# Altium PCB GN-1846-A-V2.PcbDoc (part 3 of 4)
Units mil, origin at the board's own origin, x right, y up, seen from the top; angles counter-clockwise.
Board outline 11624.17 x 2384.02 mil, 4 copper layers (Top, GND, VCC, Bottom), stack 40.7 mil thick; 450 components, 346 nets, 1652 pads, 832 vias.
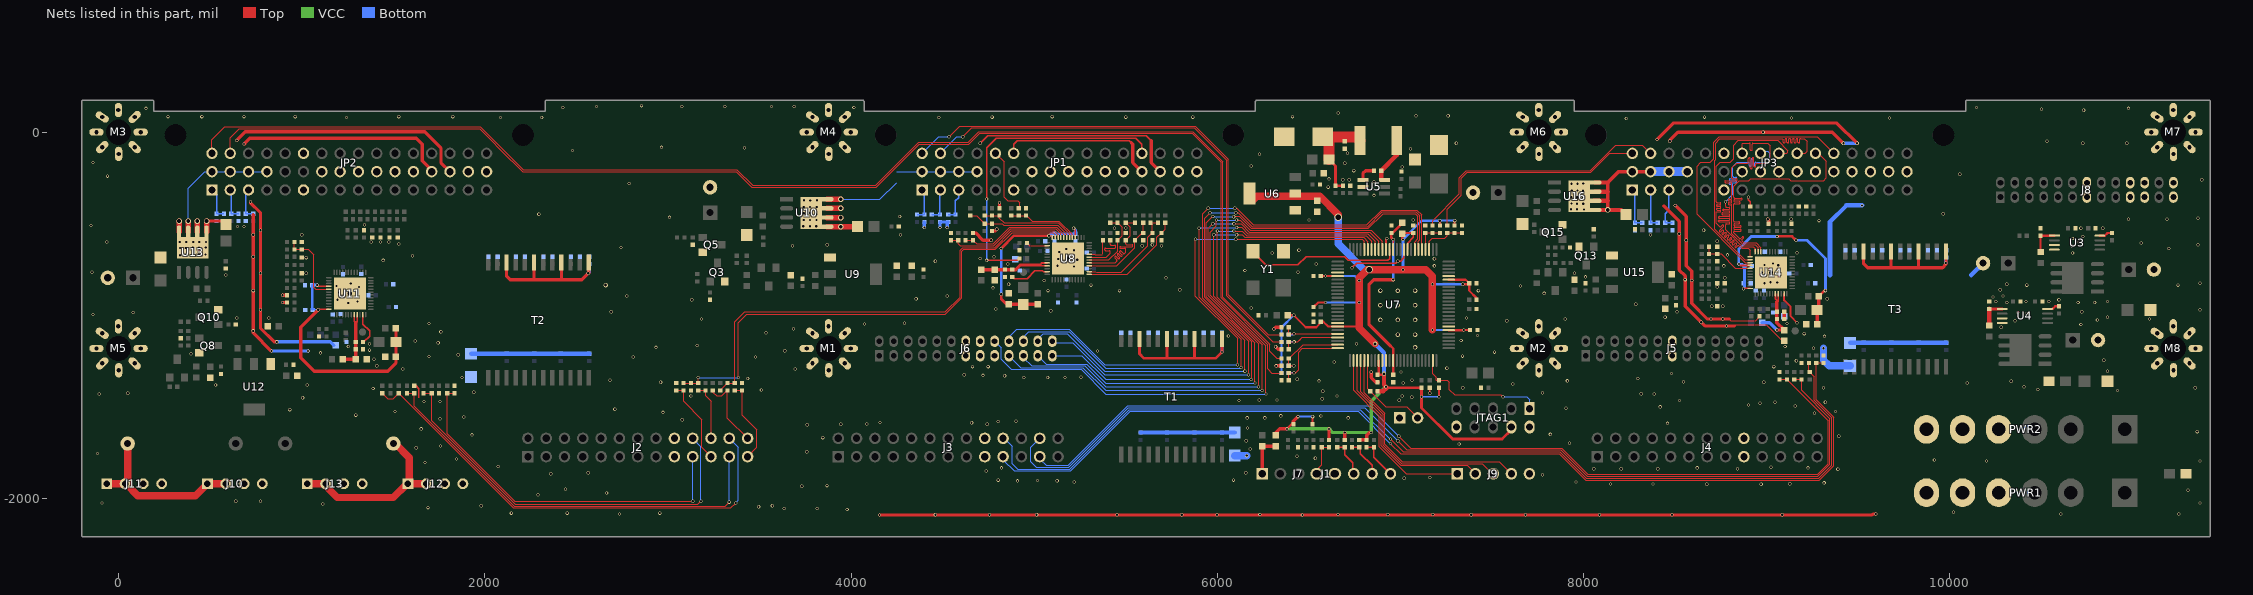
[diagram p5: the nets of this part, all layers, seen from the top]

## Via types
v1: diameter 18, hole 12, Top to Bottom, 768 vias
v2: diameter 24, hole 16, Top to Bottom, 34 vias
v3: diameter 30, hole 20, Top to Bottom, 27 vias
v4: diameter 40, hole 30, Top to Bottom, 2 vias
v5: diameter 24, hole 14, Top to Bottom, 1 vias

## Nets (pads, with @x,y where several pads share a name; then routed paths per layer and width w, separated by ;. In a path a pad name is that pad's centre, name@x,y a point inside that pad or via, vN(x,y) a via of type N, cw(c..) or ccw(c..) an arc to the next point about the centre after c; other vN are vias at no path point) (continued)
CRGMII_TXCKOUT: JP3.A11 U14.22 | length 1539.2
  Top w5: U14.22@8968.27,-651.89 8968.27,-630 8943.27,-605 8875,-605 8863.79,-593.79 cw(c8866.97,-590.61) 8863.79,-587.42 8871.82,-579.39 ccw(c8868.64,-576.21) 8871.82,-573.03 8871.11,-572.32 ccw(c8867.93,-575.5) 8864.75,-572.32 8856.72,-580.35 cw(c8853.54,-577.17) 8850.35,-580.35 8820,-550 8820,-544.5 cw(c8824.5,-544.5) 8824.5,-540 8855.5,-540 ccw(c8855.5,-535.5) 8860,-535.5 8860,-534.5 ccw(c8855.5,-534.5) 8855.5,-530 8824.5,-530 cw(c8824.5,-525.5) 8820,-525.5 8820,-524.5 cw(c8824.5,-524.5) 8824.5,-520 8855.5,-520 ccw(c8855.5,-515.5) 8860,-515.5 8860,-514.5 ccw(c8855.5,-514.5) 8855.5,-510 8824.5,-510 cw(c8824.5,-505.5) 8820,-505.5 8820,-504.5 cw(c8824.5,-504.5) 8824.5,-500 8846.87,-500 ccw(c8846.87,-495.5) 8851.37,-495.5 8851.37,-494.5 ccw(c8846.87,-494.5) 8846.87,-490 8824.5,-490 cw(c8824.5,-485.5) 8820,-485.5 8820,-394.5 cw(c8824.5,-394.5) 8824.5,-390 8849.56,-390 ccw(c8849.56,-385.5) 8854.06,-385.5 8854.06,-384.5 ccw(c8849.56,-384.5) 8849.56,-380 8824.5,-380 cw(c8824.5,-375.5) 8820,-375.5 8820,-374.5 cw(c8824.5,-374.5) 8824.5,-370 8860.5,-370 ccw(c8860.5,-365.5) 8865,-365.5 8865,-364.5 ccw(c8860.5,-364.5) 8860.5,-360 8824.5,-360 cw(c8824.5,-355.5) 8820,-355.5 8820,-295 8850,-265 8902.13,-265 8912.13,-255 9120,-255 9130,-265 9310,-265 9325,-250 9325,-160 9273.14,-108.14 JP3.A11@9265.75,-115.52
CRGMII_TXD0: JP3.A7 U14.23 | length 1537.8
  Top w5: 8770,-270.5 ccw(c8774.5,-270.5) 8774.5,-275 8805.5,-275 cw(c8805.5,-279.5) 8810,-279.5 8810,-360.5 cw(c8805.5,-360.5) 8805.5,-365 8793.73,-365 ccw(c8793.73,-369.5) 8789.23,-369.5 ; 8770,-269.5 cw(c8774.5,-269.5) 8774.5,-265 8834,-265 ccw(c8834,-260.5) 8838.5,-260.5 ; 8789.23,-390.5 ccw(c8793.73,-390.5) 8793.73,-395 8805.5,-395 cw(c8805.5,-399.5) 8810,-399.5 8810,-554.14 8870.86,-615 8937.52,-615 8952.52,-630 U14.23@8952.52,-651.89 ; 8789.23,-389.5 cw(c8793.73,-389.5) 8793.73,-385 8805.5,-385 ccw(c8805.5,-380.5) 8810,-380.5 ; 8789.23,-370.5 ccw(c8793.73,-370.5) 8793.73,-375 8805.5,-375 cw(c8805.5,-379.5) 8810,-379.5 ; 8838.5,-259.5 ccw(c8834,-259.5) 8834,-255 8814.5,-255 cw(c8814.5,-250.5) 8810,-250.5 8810,-195 8835,-170 8895.5,-170 ccw(c8895.5,-165.5) 8900,-165.5 8900,-144.5 cw(c8904.5,-144.5) 8904.5,-140 8905.5,-140 cw(c8905.5,-144.5) 8910,-144.5 8910,-195.5 ccw(c8914.5,-195.5) 8914.5,-200 8915.5,-200 ccw(c8915.5,-195.5) 8920,-195.5 8920,-144.5 cw(c8924.5,-144.5) 8924.5,-140 8925.5,-140 cw(c8925.5,-144.5) 8930,-144.5 8930,-184.96 ccw(c8934.5,-184.96) 8934.5,-189.46 8935.5,-189.46 ccw(c8935.5,-184.96) 8940,-184.96 8940,-174.5 cw(c8944.5,-174.5) 8944.5,-170 9005,-170 9020,-155 9020,-75 9005,-60 8924.5,-60 ccw(c8924.5,-64.5) 8920,-64.5 8920,-95.5 cw(c8915.5,-95.5) 8915.5,-100 8914.5,-100 cw(c8914.5,-95.5) 8910,-95.5 8910,-64.5 ccw(c8905.5,-64.5) 8905.5,-60 8870,-60 8865.75,-64.25 JP3.A7@8865.75,-118.39
CRGMII_TXD1: JP3.A8 U14.24 | length 1563.4
  Top w5: v1(8775,-380) 8775,-405.5 ccw(c8779.5,-405.5) 8779.5,-410 8794.31,-410 cw(c8794.31,-414.5) 8798.81,-414.5 8798.81,-415.5 cw(c8794.31,-415.5) 8794.31,-420 8765.19,-420 ccw(c8765.19,-424.5) 8760.69,-424.5 8760.69,-425.5 ccw(c8765.19,-425.5) 8765.19,-430 8794.31,-430 cw(c8794.31,-434.5) 8798.81,-434.5 8798.81,-435.5 cw(c8794.31,-435.5) 8794.31,-440 8759.46,-440 ccw(c8759.46,-444.5) 8754.96,-444.5 8754.96,-445.5 ccw(c8759.46,-445.5) 8759.46,-450 8794.31,-450 cw(c8794.31,-454.5) 8798.81,-454.5 8798.81,-455.5 cw(c8794.31,-455.5) 8794.31,-460 8740.69,-460 ccw(c8740.69,-464.5) 8736.19,-464.5 8736.19,-465.5 ccw(c8740.69,-465.5) 8740.69,-470 8794.31,-470 cw(c8794.31,-474.5) 8798.81,-474.5 8798.81,-475.5 cw(c8794.31,-475.5) 8794.31,-480 8740.69,-480 ccw(c8740.69,-484.5) 8736.19,-484.5 8736.19,-485.5 ccw(c8740.69,-485.5) 8740.69,-490 8794.31,-490 cw(c8794.31,-494.5) 8798.81,-494.5 8798.81,-495.5 cw(c8794.31,-495.5) 8794.31,-500 8779.5,-500 ccw(c8779.5,-504.5) 8775,-504.5 8775,-533.28 8866.72,-625 8925,-625 8936.78,-636.78 U14.24@8936.78,-651.89
  Bottom w5: v1(8775,-380) 8815,-340 8815,-289.5 ccw(c8810.5,-289.5) 8810.5,-285 8799.5,-285 cw(c8799.5,-280.5) 8795,-280.5 8795,-279.5 cw(c8799.5,-279.5) 8799.5,-275 8830.5,-275 ccw(c8830.5,-270.5) 8835,-270.5 8835,-269.5 ccw(c8830.5,-269.5) 8830.5,-265 8799.5,-265 cw(c8799.5,-260.5) 8795,-260.5 8795,-259.5 cw(c8799.5,-259.5) 8799.5,-255 8830.5,-255 ccw(c8830.5,-250.5) 8835,-250.5 8835,-249.5 ccw(c8830.5,-249.5) 8830.5,-245 8819.5,-245 cw(c8819.5,-240.5) 8815,-240.5 8815,-190 8840,-165 8900.5,-165 cw(c8900.5,-169.5) 8905,-169.5 8905,-180.5 ccw(c8909.5,-180.5) 8909.5,-185 8910.5,-185 ccw(c8910.5,-180.5) 8915,-180.5 8915,-149.5 cw(c8919.5,-149.5) 8919.5,-145 8920.5,-145 cw(c8920.5,-149.5) 8925,-149.5 8925,-180.5 ccw(c8929.5,-180.5) 8929.5,-185 8930.5,-185 ccw(c8930.5,-180.5) 8935,-180.5 8935,-169.5 cw(c8939.5,-169.5) 8939.5,-165 9010,-165 9015,-160 9015,-115 9005,-105 8976.27,-105 JP3.A8@8965.75,-115.52
CRGMII_TXD2: JP3.A9 U14.25 | length 1555.2
  Top w5: 8725,-420.5 ccw(c8729.5,-420.5) 8729.5,-425 8745.42,-425 cw(c8745.42,-429.5) 8749.92,-429.5 ; 8725,-419.5 cw(c8729.5,-419.5) 8729.5,-415 8745.42,-415 ccw(c8745.42,-410.5) 8749.92,-410.5 ; 8725,-400.5 ccw(c8729.5,-400.5) 8729.5,-405 8745.42,-405 cw(c8745.42,-409.5) 8749.92,-409.5 ; 8725,-399.5 cw(c8729.5,-399.5) 8729.5,-395 8745.42,-395 ccw(c8745.42,-390.5) 8749.92,-390.5 ; 8749.92,-430.5 cw(c8745.42,-430.5) 8745.42,-435 8725,-435 8725,-497.43 8742.82,-515.25 ccw(c8746,-512.06) 8749.18,-515.25 8756.61,-507.82 cw(c8759.79,-511) 8762.98,-507.82 8763.68,-508.52 cw(c8760.5,-511.7) 8763.68,-514.89 8742.04,-536.53 ccw(c8745.22,-539.72) 8742.04,-542.9 8742.74,-543.6 ccw(c8745.93,-540.42) 8749.11,-543.6 8756.96,-535.75 cw(c8760.14,-538.93) 8763.32,-535.75 8764.03,-536.46 cw(c8760.85,-539.64) 8764.03,-542.82 8756.18,-550.68 ccw(c8759.36,-553.86) 8756.18,-557.04 8756.89,-557.75 ccw(c8760.07,-554.56) 8763.25,-557.75 8771.1,-549.89 cw(c8774.29,-553.08) 8777.47,-549.89 8778.17,-550.6 cw(c8774.99,-553.78) 8778.17,-556.96 8770.32,-564.82 ccw(c8773.5,-568) 8770.32,-571.18 8771.03,-571.89 ccw(c8774.21,-568.71) 8777.39,-571.89 8785.25,-564.04 cw(c8788.43,-567.22) 8791.61,-564.04 8792.32,-564.74 cw(c8789.13,-567.92) 8792.32,-571.11 8784.46,-578.96 ccw(c8787.65,-582.14) 8784.46,-585.32 8785.17,-586.03 ccw(c8788.35,-582.85) 8791.53,-586.03 8799.39,-578.18 cw(c8802.57,-581.36) 8805.75,-578.18 8806.46,-578.88 cw(c8803.28,-582.07) 8806.46,-585.25 8798.61,-593.1 ccw(c8801.79,-596.28) 8798.61,-599.47 8799.31,-600.17 ccw(c8802.49,-596.99) 8805.68,-600.17 8813.53,-592.32 cw(c8816.71,-595.5) 8819.89,-592.32 8820.6,-593.03 cw(c8817.42,-596.21) 8820.6,-599.39 8812.75,-607.24 ccw(c8815.93,-610.43) 8812.75,-613.61 8813.45,-614.32 ccw(c8816.64,-611.13) 8819.82,-614.32 8827.67,-606.46 cw(c8830.85,-609.64) 8834.04,-606.46 8834.74,-607.17 cw(c8831.56,-610.35) 8834.74,-613.53 8826.89,-621.39 ccw(c8830.07,-624.57) 8826.89,-627.75 8827.6,-628.46 ccw(c8830.78,-625.28) 8833.96,-628.46 8841.81,-620.6 cw(c8845,-623.79) 8848.18,-620.6 8862.57,-635 8900,-635 8908.43,-643.43 U14.25@8908.43,-680.24 ; 8749.92,-389.5 ccw(c8745.42,-389.5) 8745.42,-385 8729.5,-385 cw(c8729.5,-380.5) 8725,-380.5 8725,-185 8745,-165 8800,-165 8820,-145 8820,-70 8845,-45 9060,-45 9115,-100 9115,-110 9109.48,-115.52 JP3.A9@9065.75,-115.52
CRGMII_TXD3: JP3.A10 U14.26 | length 1560.5
  Top w5: U14.26@8908.43,-695.98 8880.98,-695.98 8715,-530 8715,-154.14 8720,-149.14 8720,-59.14 8744.14,-35 9085,-35 9090,-40 9090,-54.02 ccw(c9094.5,-54.02) 9094.5,-58.52 9095.5,-58.52 ccw(c9095.5,-54.02) 9100,-54.02 9100,-39.5 cw(c9104.5,-39.5) 9104.5,-35 9105.5,-35 cw(c9105.5,-39.5) 9110,-39.5 9110,-54.02 ccw(c9114.5,-54.02) 9114.5,-58.52 9115.5,-58.52 ccw(c9115.5,-54.02) 9120,-54.02 9120,-39.5 cw(c9124.5,-39.5) 9124.5,-35 9125.5,-35 cw(c9125.5,-39.5) 9130,-39.5 9130,-54.02 ccw(c9134.5,-54.02) 9134.5,-58.52 9135.5,-58.52 ccw(c9135.5,-54.02) 9140,-54.02 9140,-39.5 cw(c9144.5,-39.5) 9144.5,-35 9145.5,-35 cw(c9145.5,-39.5) 9150,-39.5 9150,-54.02 ccw(c9154.5,-54.02) 9154.5,-58.52 9155.5,-58.52 ccw(c9155.5,-54.02) 9160,-54.02 9160,-39.5 cw(c9164.5,-39.5) 9164.5,-35 9165.5,-35 cw(c9165.5,-39.5) 9170,-39.5 9170,-54.02 ccw(c9174.5,-54.02) 9174.5,-58.52 9175.5,-58.52 ccw(c9175.5,-54.02) 9180,-54.02 9180,-39.5 cw(c9184.5,-39.5) 9184.5,-35 9205,-35 9220,-50 9220,-105 9209.48,-115.52 JP3.A10@9165.75,-115.52
CRGMII_TXEN: JP3.A12 U14.27 | length 1563.4
  Top w5: U14.27@8908.43,-711.73 8882.59,-711.73 8620,-449.14 8620,-185 8640,-165 8690,-165 8710,-145 8710,-55 8740,-25 9275.62,-25 JP3.A12@9365.75,-115.13
EPHY_CLK: JP1.A13 R39.1 | length 1731.5
  Top w8: v1(4740,-700) 4910,-700 R39.1@4920,-690 ; v1(4740,-365) 4740,-85 4791.85,-33.15 5555.11,-33.15 5587.8,-65.84 JP1.A13@5587.8,-115.41
  Bottom w8: v1(4740,-700) v1(4740,-365)
EPHY_RSTN: JP1.A5 R35.1 | length 386.6
  Top w5: JP1.A5@4787.8,-115.41 4835,-162.61 4835,-355 4855,-375 4910,-375 4920,-385 R35.1@4920,-415
F3V3A: B2.2 C26.1 C27.1 U7.13 U7.63 | length 1088.8
  Top w8: C26.1@6950,-550 C26.1@6955.47,-550 ; U7.63@6959.81,-640.27 6960,-640.08 v1(6960,-585.84)
  Top w12: 6943.15,-1165.84 6944.81,-1165.84 6959.81,-1180.84 U7.13@6959.81,-1246.56 C27.1@6959.81,-1324.81
  Top w15: C26.1@6950,-550 6950,-575.84 v1(6960,-585.84) ; C26.1@6955.47,-550 B2.2@7010,-495.47
  Top w18: 6943.15,-1165.84 6828.15,-1050.84 6828.15,-830 6853.15,-805 v1(6960,-805)
  Bottom w15: v1(6960,-805) v1(6960,-585.84)
F3V3D: B1.1 B2.1 B13.2 C14.1 C15.1 C21.1 C22.1 C23.1 C24.1 C25.1 JTAG1.4 R17.1 R19.1 R20.1 R23.2 R300.1 R301.1 R302.1 R304.1 R426.2 R427.2 R428.2 R429.2 R430.2 R431.2 R432.1 R433.1 R500.2 U6.2 U6.4 U7.9 U7.31 U7.45 U7.59 U7.80 U7.94 | length 7436.6
  Top w8: U7.59@7038.55,-640.27 7038.55,-606.45 7070,-575 C25.1@7070,-550
  Top w10: C24.1@6565,-785 v1(6590,-785) ; v1@6590.94,-785.94 U7.80@6656.66,-785.94 ; v1(7210,-1445) R19.1@7210,-1395
  Top w12: v1(6380,-1620) R432.1@6405,-1595 ; B1.1@6393,-1000 B1.1@6384.53,-1000 v1(6417,-1000) 6482,-1065 6540,-1065 6565,-1040 C21.1@6565,-1035 6578.47,-1035 6605,-1061.53 6773.47,-1061.53 ; R433.1@6520,-1595 v1(6520,-1553) ; R17.1@6525,-955 6550,-930 v1(6590,-930) ; C23.1@6880,-1325 6881.07,-1323.93 U7.9@6881.07,-1246.56 ; B2.1@7010,-554.53 7014.53,-550 C25.1@7070,-550 ; R431.2@7215,-510 v1@7215,-485 ; U7.31@7262.96,-1081.21 v1@7343.79,-1081.21 ; U7.45@7262.96,-805.62 7355.62,-805.62 C15.1@7375,-825 7375,-865 7415,-905 R23.2@7415,-915 ; R430.2@7295,-510 v1@7295,-484 ; v1(7345,-1080) C22.1@7380,-1080
  Top w15: C23.1@6880,-1325 v2@6905,-1325 ; v1@6925,-1395 R20.1@7115,-1395 v1(7115,-1445) 7115,-1505 7285,-1675 7555,-1675 7605,-1625 JTAG1.4@7605,-1610 ; v1@7010,-582.69 B2.1@7010,-554.53 ; v1(7340,-830) C15.1@7370,-830
  Top w18: B13.2@6320,-1655.47 6320,-1640 6340,-1620 v1(6380,-1620) ; R432.1@6415,-1595 6415,-1578 v1(6440,-1553) ; R302.1@6610,-1680 v1(6610,-1620) ; R301.1@6695,-1680 v1(6695,-1640) ; R300.1@6775,-1680 R304.1@6815,-1680 6815,-1655 6830,-1640
  Top w24: R500.2@6875,-1415 6905,-1415 v1@6925,-1395 ; v2(6910,-1320) 6910,-1380.11 6919.94,-1390.06 v1@6924.89,-1395
  Top w40: U6.4@6195,-370 6215,-350 6560,-350 v4@6660,-450 ; 6773.15,-1067.92 v2(6861.07,-1155.84) ; 6775,-1060 6775,-793.99 v4@6818.15,-750.84 ; v4@6830,-750.84 v1(7013.15,-750.84) 7138.15,-750.84 7173.15,-785.84 v1@7173.15,-1080
  VCC w18: v1(6380,-1620) v1(6610,-1620) 6630,-1640 v1(6695,-1640) v1(6840,-1640) 6840,-1470 v1(6920,-1390)
  Bottom w10: v1(7115,-1445) v1(7210,-1445)
  Bottom w12: R429.2@6350,-1315 R426.2@6350,-1105 6350,-1067 v1(6417,-1000) ; v1(6440,-1553) v1(6520,-1553) ; v1(6590,-930) v1@6770,-930 ; v1(6590,-785) 6750,-785 v1(6775,-810) ; v1(7013.15,-585.84) 7114.99,-484 v1(7214,-484) ; v1(7175,-1080) v1(7345,-1080) ; v1@7215,-483 v1(7296,-483)
  Bottom w15: v1(7013.15,-750.84) v1(7013.15,-585.84) ; v1(7175,-830) v1(7340,-830)
  Bottom w24: v2(6861.07,-1155.84) 6910,-1204.77 v2(6910,-1320)
  Bottom w40: v4(6660,-465) 6660,-610 6800,-750
  other v1: 6775,-930
  other v4: 6830,-750
F_25MHZ: U7.64 Y1.3 | length 866.2
  Top w8: Y1.3@6204.61,-639.69 6204.61,-664.61 6265,-725 6440,-725 6485,-680 6695,-680 6715,-700 6930,-700 6940.12,-689.88 U7.64@6940.12,-640.27
G0_UART_RX: R75.2 R421.1 R426.1 U7.96 | length 338
  Top w5: R421.1@6390,-1065 R75.2@6390,-1105 6394.1,-1100.9 6418,-1100.9 U7.96@6656.66,-1100.9
  Bottom w8: R426.1@6390,-1105 6414,-1105 v1(6418,-1101)
G0_UART_TX: R76.2 R420.1 R427.1 U7.97 | length 366.2
  Top w5: R420.1@6390,-1185 R76.2@6390,-1145 v1(6419,-1145) 6438.58,-1145 6463,-1120.58 ; 6448.58,-1135 6463,-1120.58 ; U7.97@6656.66,-1120.58 6463,-1120.58
  Bottom w8: R427.1@6390,-1145 v1(6419,-1145)
G1_UART_RX: R135.2 R422.1 R428.1 U7.99 | length 381.7
  Top w5: R422.1@6390,-1265 R135.2@6390,-1235 6393.14,-1235 6468.19,-1159.95 U7.99@6656.66,-1159.95
  Top w8: R422.1@6390,-1275 v1(6417,-1275)
  Bottom w8: R428.1@6390,-1275 v1(6417,-1275)
G1_UART_TX: R137.2 R423.1 R429.1 U7.100 | length 438.6
  Top w5: R423.1@6390,-1345 6390,-1314 v1(6418,-1314) 6427,-1314 6443,-1298 6443,-1201 6464.36,-1179.64 U7.100@6656.66,-1179.64
  Bottom w8: R429.1@6390,-1315 6391,-1314 v1(6418,-1314)
G2_UART_RX: R195.2 R419.1 R430.1 U7.53 | length 252
  Top w5: U7.53@7156.66,-640.27 7156.66,-594.34 7172,-579 7242,-579 7255,-566 R195.2@7255,-550 R419.1@7335,-550
G2_UART_TX: R196.2 R418.1 R431.1 U7.54 | length 173.6
  Top w5: R418.1@7135,-550 R418.1@7145,-550 ; U7.54@7136.97,-640.27 7136.97,-558.03 R418.1@7145,-550 ; R431.1@7215,-550 R196.2@7175,-550 R418.1@7145,-550
GE0_ENREG: R48.1 U8.38 | length 115.9
  Top w5: R48.1@4960,-605 4974.13,-619.13 5001.82,-619.13 U8.38@5070.04,-619.13
GE0_INT_N: R46.1 U8.20 | length 152.4
  Top w5: U8.20@5299.96,-666.38 5329.07,-666.38 5331.85,-669.16 5370,-669.16 5375,-664.16 R46.1@5375,-590
GE0_LED0: R42.1 R44.1 R52.1 U8.34 | length 2575
  Top w5: R52.1@3285,-1410 R42.1@3325,-1370 R44.1@3365,-1370 3365,-1035 3420,-980 4515,-980 4595,-900 4595,-645.86 4610.86,-630 4783.28,-630 4874.78,-538.5 5108.5,-538.5 5129.88,-559.88 U8.34@5129.88,-575.04
GE0_LED1: R37.1 R38.1 R55.1 U8.35 | length 2731.9
  Top w5: R38.1@3085,-1370 R37.1@3165,-1370 v1@3165,-1345 ; v1(3385,-1340) 3385,-1040 3430,-995 4514.14,-995 4605,-904.14 4605,-650 4615,-640 4787.43,-640 4878.93,-548.5 5103.5,-548.5 5114.13,-559.13 U8.35@5114.13,-575.04
  Bottom w5: v1(3165,-1340) 3340,-1340 ; 3345,-1340 3340,-1340 ; v1(3385,-1340) 3340,-1340
GE0_LED2: R63.1 R64.1 U8.32 | length 616.9
  Top w5: R63.1@4625,-590 R64.1@4665,-590 4685,-610 4775,-610 4866.5,-518.5 5123.5,-518.5 5161.38,-556.38 U8.32@5161.38,-575.04
GE0_PME: R50.1 R51.1 U8.33 | length 693.3
  Top w5: R51.1@4545,-590 R50.1@4585,-590 4585,-610 4595,-620 4779.14,-620 4870.64,-528.5 5118.5,-528.5 5145.63,-555.63 U8.33@5145.63,-575.04
GE0_RXCLK: R27.2 U8.19 | length 300.7
  Top w5: U8.19@5299.96,-682.13 5392.87,-682.13 5415,-660 5415,-652.75 ccw(c5409.75,-652.75) 5409.75,-647.5 5390.25,-647.5 cw(c5390.25,-642.25) 5385,-642.25 5385,-637.75 cw(c5390.25,-637.75) 5390.25,-632.5 5439.75,-632.5 ccw(c5439.75,-627.25) 5445,-627.25 5445,-622.75 ccw(c5439.75,-622.75) 5439.75,-617.5 5420.25,-617.5 cw(c5420.25,-612.25) 5415,-612.25 R27.2@5415,-590
GE0_RXCTL: R28.2 R56.1 U8.13 | length 575.6
  Top w5: U8.13@5299.96,-776.61 5329.3,-776.61 5508.39,-776.61 5670,-615 5670,-575 R56.1@5695,-550 5715,-530 R28.2@5715,-495
GE0_RXD0: R29.2 R59.1 R61.1 U8.14 | length 561.3
  Top w5: U8.14@5299.96,-760.87 5328.56,-760.87 5335.87,-760.87 5340,-765 5475,-765 5620,-620 5620,-575 R61.1@5645,-550 5645,-505 R59.1@5635,-495 R29.2@5675,-495
GE0_RXD1: R30.2 R66.1 R67.1 U8.16 | length 447.8
  Top w5: U8.16@5299.96,-729.37 5372.06,-729.37 5450.63,-729.37 5550,-630 R30.2@5550,-590 5590,-550 R67.1@5595,-550 R66.1@5595,-495
GE0_RXD2: R31.2 R68.1 R70.1 U8.17 | length 716.5
  Top w5: U8.17@5299.96,-713.62 5371.31,-713.62 5441.38,-713.62 5450.5,-704.5 ccw(c5446.97,-700.96) 5450.5,-697.43 5439.86,-686.79 cw(c5443.4,-683.25) 5439.86,-679.72 cw(c5443.4,-683.25) 5446.93,-679.72 5457.57,-690.36 ccw(c5461.11,-686.82) 5464.64,-690.36 ccw(c5461.11,-686.82) 5464.64,-683.28 5454,-672.64 cw(c5457.54,-669.11) 5454,-665.57 cw(c5457.54,-669.11) 5461.08,-665.57 5471.72,-676.21 ccw(c5475.25,-672.68) 5478.79,-676.21 ccw(c5475.25,-672.68) 5478.79,-669.14 5466.79,-657.15 cw(c5470.33,-653.61) 5466.79,-650.08 cw(c5470.33,-653.61) 5473.86,-650.08 5485.86,-662.07 ccw(c5489.39,-658.54) 5492.93,-662.07 5500,-655 5500,-640 ccw(c5495,-640) 5495,-635 5471,-635 cw(c5471,-630) 5466,-630 cw(c5471,-630) 5471,-625 5534,-625 ccw(c5534,-620) 5539,-620 ccw(c5534,-620) 5534,-615 5505,-615 cw(c5505,-610) 5500,-610 R70.1@5500,-590 5525,-565 5525,-520 R68.1@5500,-495 R31.2@5550,-495
GE0_RXD3: R33.2 R71.1 R72.1 U8.18 | length 390
  Top w5: U8.18@5299.96,-697.87 5406.15,-697.87 5455,-649.02 R72.1@5455,-590 5480,-565 5480,-520 R71.1@5455,-495 R33.2@5415,-495
GND: C1.2 C2.2 C3.2 C5.2 C6.2 C9.2 C10.2 C12.2 C13.2 C14.2 C15.2 C16.2 C17.2 C18.2 C19.2 C20.1 C21.2 C22.2 C23.2 C24.2 C25.2 C26.2 C27.2 C28.2 C29.2 C30.2 C31.2 C32.2 C33.2 C34.2 C35.2 C36.2 C37.2 C38.2 C39.2 C40.2 C41.2 C42.2 C43.2 C44.2 C45.1 C46.1 C47.2 C48.1 C49.1 C50.1 C51.1 C52.1 C53.1 C54.1 C55.2 C56.2 C57.2 C58.2 C59.1 C60.1 C61.2 C62.2 C63.2 C64.2 C65.2 C66.2 C67.2 C68.2 C69.2 C70.2 C71.2 C72.2 C73.2 C74.2 C75.2 C76.2 C77.2 C78.1 C79.1 C80.1 C81.1 C82.1 C83.1 C84.1 C85.1 C86.2 C87.2 C88.1 C89.2 C90.2 C91.2 C92.2 C93.1 C94.1 C95.2 C96.2 C97.2 C98.2 C99.2 C100.2 C101.2 C102.2 C103.2 C104.2 C105.2 C106.2 C107.2 C108.2 C109.2 C110.2 C111.2 C112.2 C113.1 C114.1 C115.1 C116.1 C117.1 C118.1 C119.1 C120.1 C121.2 C122.1 C123.2 C124.2 C125.2 C126.2 C127.1 C128.1 C129.2 C300.2 C301.2 C302.2 C303.2 C304.2 C305.2 J1.5 J2.17 J2.18 J3.17 J3.18 J4.17 J4.18 J5.13 J5.14 J6.13 J6.14 J6.15 J6.16 J6.17 J7.5 J8.13 J8.14 J8.19 J8.20 J8.21 J8.22 J8.25 J8.26 J9.5 J10.3 J10.4 J11.3 J11.4 J12.3 J12.4 J13.3 J13.4 J14.1 JP1.A6 JP1.B7 JP1.B8 JP1.B9 JP1.B10 JP1.B11 JP1.B12 JP1.B13 JP1.B14 JP1.B15 JP1.B16 JP1.C6 JP2.A6 JP2.B7 JP2.B8 JP2.B9 JP2.B10 JP2.B11 JP2.B12 JP2.B13 JP2.B14 JP2.B15 JP2.B16 JP2.C6 JP3.A6 JP3.B7 JP3.B8 JP3.B9 JP3.B10 JP3.B11 JP3.B12 JP3.B13 JP3.B14 JP3.B15 JP3.B16 JP3.C6 JTAG1.2 JTAG1.10 M1.2 M1.3 M1.4 M1.5 M1.6 M1.7 M1.8 M1.9 M2.2 M2.3 M2.4 M2.5 M2.6 M2.7 M2.8 M2.9 M3.2 M3.3 M3.4 M3.5 M3.6 M3.7 M3.8 M3.9 M4.2 M4.3 M4.4 M4.5 M4.6 M4.7 M4.8 M4.9 M5.2 M5.3 M5.4 M5.5 M5.6 M5.7 M5.8 M5.9 M6.2 M6.3 M6.4 M6.5 M6.6 M6.7 M6.8 M6.9 M7.2 M7.3 M7.4 M7.5 M7.6 M7.7 M7.8 M7.9 M8.2 M8.3 M8.4 M8.5 M8.6 M8.7 M8.8 M8.9 PWR1.4 PWR1.5 PWR1.6 PWR2.4 PWR2.5 PWR2.6 Q3.2 Q5.2 Q8.2 Q10.2 Q13.2 Q15.2 R1.2 R4.2 R5.2 R6.2 R7.1 R11.2 R18.1 R21.2 R22.2 R40.1 R43.1 R45.1 R51.2 R55.2 R56.2 R61.2 R64.2 R67.2 R70.2 R72.2 R74.1 R81.1 R83.1 R100.1 R101.1 R105.1 R111.2 R115.2 R116.2 R121.2 R125.2 R126.2 R130.2 R132.2 R134.1 R141.1 R143.1 R160.1 R161.1 R165.1 R171.2 R175.2 R176.2 R181.2 R184.2 R187.2 R190.2 R192.2 R194.1 R201.1 R203.1 R400.2 R401.2 R402.2 R403.2 R404.2 R405.2 R406.2 R407.2 R408.2 R418.2 R419.2 R420.2 R421.2 R422.2 R423.2 R424.1 R425.1 U3.3 U3.4 U4.3 U4.4 U5.2 U6.1 U7.10 U7.11 U7.32 U7.46 U7.60 U7.65 U7.79 U7.93 U8.47 U8.49 U9.1 U11.47 U11.49 U12.1 U14.47 U14.49 U15.1 Y1.2 | length 19255.5
  Top w5: 7177.52,-722.52 v1(7185,-730) v1@7190.5,-730 ; v1(7184.78,-691.04) 7195.4,-691.04 ; 8795,-1020 8803.5,-1028.5 8940,-1028.5 8960,-1008.5 R160.1@8960,-1005 ; 8815,-1060 8817,-1058 8823.5,-1051.5 8996.5,-1051.5 9084.53,-1139.53 C98.2@9095,-1139.53
  Top w8: U11.47@1334.02,-995.8 1334.02,-1048.68 1370.42,-1085.08 1370.42,-1114.58 C63.2@1340,-1145 ; R105.1@1615,-1385 1625,-1385 1640,-1400 1640,-1450 ; v1(4705,-60) 4745,-20 5612.39,-20 5638.23,-45.84 ; C28.2@4880,-790 4890.09,-800.09 4961.19,-800.09 5004.02,-757.26 5045.97,-757.26 5049.58,-760.87 U8.47@5070.04,-760.87 ; JP1.A6@4887.8,-115.41 4887.8,-67.2 4907.66,-47.34 5519.65,-47.34 5530.65,-58.34 ; v1(6735,-740) 6760,-715 6975,-715 v1(6985,-705) 7000,-705 7018.86,-686.14 U7.60@7018.86,-640.27 ; v1(7160,-1425) R21.2@7160,-1395 ; v1(8900,-355) 8900,-370 8910,-380 R192.2@8910,-405
  Top w10: U7.65@6920,-640.71 U7.65@6920.44,-640.27 v1@6920.44,-585.84 ; v1@7183.87,-690.13 v1(7184.78,-691.04) ; U14.47@9094.26,-881.81 9094.26,-918.33 9130,-954.07 9130,-1005 v1(9165,-1040)
  Top w18: v1(645,-45) 692.5,2.5 1672.21,2.5 1760.55,-85.84 1760.55,-165.84 JP2.B14@1809.84,-215.13 ; v1(720,-380) 720,-384.54 775,-439.54 v1(775,-535) v1(775,-770) v1(775,-970) 775,-1070 850,-1145 v1(864,-1145) ; 735,-450.46 v1(735,-560) v1(735,-680) v1(735,-865) v1(735,-1085) 735,-1095 v1(835,-1195) ; v1(895,-930) R111.2@920,-930 ; v1(895,-890) R125.2@920,-890 ; JP2.B13@1709.84,-215.13 1708.15,-213.44 1708.15,-205.84 1658.15,-155.84 1658.15,-65.84 1625.81,-33.5 716.5,-33.5 v1@688.99,-61.01 ; v1(4154.8,-2089.8) 4460,-2089.8 4756,-2089.8 5013,-2089.8 5452,-2089.8 5805,-2089.8 5998,-2089.8 6232,-2089.8 v1(6464,-2089.8) 6659,-2089.8 6930,-2089.8 7176,-2089.8 7386,-2089.8 7682,-2089.8 8087,-2089.8 8482,-2089.8 9084,-2089.8 9575,-2089.8 9579.8,-2085 v1(9595,-2085) ; R64.2@4665,-550 4680,-550 4720,-590 v1(4765,-590) ; C60.1@4770,-540 4785,-540 v1(4795,-530) ; C59.1@4810,-415 v1(4810,-385) ; 5530.65,-58.34 5538.15,-65.84 5538.15,-165.84 5558.11,-185.8 5558.19,-185.8 JP1.B13@5587.8,-215.41 ; 5638.23,-45.84 5638.23,-165.84 JP1.B14@5687.8,-215.41 ; v1(6308,-1075) 6318,-1065 R421.2@6350,-1065 ; v1(6318,-1172) 6331,-1185 R420.2@6350,-1185 ; v1(6321,-1276) 6322,-1275 R422.2@6350,-1275 ; v1(6840,-1310) 6840,-1340 6865,-1365 C23.2@6880,-1365 ; v1(8400,-40) 8490,50 9382.31,50 v1(9493.15,-60.84) ; 8437.27,-402.73 8522,-487.46 v1(8522,-555) 8522,-753 8554,-785 v1(8554,-805) 8554,-949.91 v1(8642,-1037.91) 8662.09,-1058 v1(8780,-1058) 8817,-1058 8823.5,-1058 ; v1(8470,-50) 8470,-45 8515,0 v1(8980,0) 9357.31,0 v1(9418.15,-60.84) ; v1(8500,-400) 8560,-460 v1(8560,-590) 8560,-730 8590,-760 v1(8590,-810) 8590,-935 8675,-1020 v1(8695,-1020) v1(8760,-1020) 8795,-1020 ; v1(9005,-475) 9010,-480 R190.2@9010,-500 ; 9095,-1006 C97.2@9095,-980 ; v1@688.99,-61.01 v1(685,-65) 688.99,-65 v1@688.99,-61.01
  Bottom w18: v1(835,-1195) v1(1035,-1195) ; v1(864,-1145) 1155.47,-1145 C77.2@1175,-1164.53 ; v1(4400,-520) R406.2@4400,-490 ; v1(4485,-520) R407.2@4485,-490 R408.2@4530,-490 4525,-495 v1(4525,-520) ; v1(9418.15,-60.84) v1(9493.15,-60.84)
  Bottom w25: 9345,-780 9345,-490 9435,-400 v1(9520,-400) ; 10116.1,-780 C3.2@10181.1,-715
  Bottom w40: C47.2@6095,-1766 v1(6160,-1766) ; v1(9310,-1180) 9310,-1245 9341,-1276 C121.2@9455,-1276
  other v1: 4460,-2089 4756,-2089 5013,-2089 5452,-2089 5805,-2089 5998,-2089 7386,-2089 7682,-2089 8087,-2089 8482,-2089 9084,-2089 6232,-2087.85 6659,-2088 6930,-2087.85 7176,-2087.85 2735,-2085 10605,-2085 11250,-2085 2145,-2080 2450,-2080 2955,-2080 10020,-2075 3978.15,-2060 3635,-2055 3815,-2055 1690,-2050 3495,-2045 1980,-2040 3570,-2040 1115,-2030 -90,-2025 11365,-2025 640,-2015 775,-2015 2290,-1980 2665,-1970 11300,-1955 2440,-1950 3730,-1932.85 3868.15,-1930 8672,-1921.85 8969,-1921.85 8147,-1921 8379,-1920.85 9125,-1919.85 9313.15,-1915 5218.15,-1910 7958.15,-1910 4908.15,-1904 5125,-1902.85 5018.15,-1902 4803.15,-1900 6088.15,-1900 7020,-1890 7160,-1885 7775,-1870 2360,-1865 2565,-1860 6155,-1860 4738.15,-1850 9388.15,-1840 8055,-1837.85 8205,-1837.85 8405,-1837.85 8840,-1837.85 4821,-1832.85 8620,-1832.85 9225,-1832.85 9023.15,-1830 2073.15,-1825 1673.15,-1804 10200,-1795 11365,-1795 9915,-1790 1845,-1785 6535,-1780 6435,-1770 -115,-1755 3758.15,-1745 6180,-1730 1626,-1722.85 1758.15,-1713 7320,-1702.85 7923.15,-1698 6158.15,-1685 3845,-1667.85 9393.15,-1660 1930,-1652.85 7818.15,-1650 11350,-1635 1653.15,-1620 6165,-1615 3760,-1597.85 3943.15,-1595 4743.15,-1595 4085,-1592.85 8458.15,-1590 4658.15,-1587 4158.15,-1585 4803.15,-1580 4900,-1577.85 3078.15,-1570 1755,-1565 6163.15,-1560 6258.15,-1560 6715,-1560 1885,-1555 6565,-1550 6346,-1549 1295,-1545 9260,-1535 2973.15,-1530 1510,-1525 9375,-1525 935,-1515 2710,-1512.85 7903.15,-1507 8418.15,-1500 9155,-1495 8900,-1490 8963.15,-1480 9045,-1475 9320,-1475 1668.15,-1470 1755,-1470 6118.15,-1465 8523.15,-1465 6993.15,-1464 6325,-1462.85 6228.15,-1462 6573.15,-1455 1005,-1450 7061,-1447.85 3125,-1440 6653.15,-1440 7010,-1440 -105,-1430 8385,-1430 8314.46,-1427.85 50,-1425 7775,-1422.85 1940,-1420 6575,-1415 10915,-1410 3510,-1407.85 10480,-1405 1390,-1400 7340,-1395 9310,-1395 11340,-1395 10405,-1390 530,-1380 1030,-1380 7613.15,-1375 7015,-1370 10095,-1370 2960,-1365 8983.15,-1365 8545,-1362.85 10335,-1360 6555,-1357.85 7911,-1357.85 2683.15,-1355 7063.15,-1355 6436,-1349 3435,-1345 8295,-1345 1875,-1340 4943.15,-1340 5073.15,-1340 5168.15,-1340 5255,-1337.85 4838.15,-1330 4720,-1327.85 4618.15,-1325 8480,-1317.85 7003.15,-1310 10860,-1305 1552,-1292.85 3695,-1292.85 7253.15,-1289 4663.15,-1280 4748.15,-1280 9038.15,-1280 1410,-1275 6638.15,-1255 9161.5,-1247.85 10840,-1245 1395,-1240 2810,-1227.85 3478.15,-1227 1695,-1225 7338,-1222.85 1855,-1215 395,-1210 1103.15,-1205 7513.15,-1201 5345,-1195 3638.15,-1193 1370,-1190 9255,-1180 2935,-1175 1255,-1170 9100,-1170 3160,-1165 1370,-1155 6760,-1155 1745,-1150 1620,-1140 7331,-1137.85 9315,-1115 6060,-1112.85 7420,-1110 9205,-1100 3535,-1095 1760,-1090 3685,-1072.85 10280,-1065 10715,-1050 4073.15,-1047 1695,-1045 9110,-1045 4291,-1042.85 7580,-1030 10355,-1030 10805,-1025 3183.15,-1020 7900,-1020 11090,-1020 645,-1015 820,-1015 7360,-1015 8445,-1010 10860,-1010 -140,-995 10420,-990 80,-985 10370,-985 2690,-980 8510,-980 10720,-980 5090,-975 11365,-970 4790,-965 6185,-960 8700,-950 8760,-950 8285,-940 1254,-932.85 10310,-930 10700,-930 10790,-930 1305,-925 10250,-925 10415,-925 10540,-925 10860,-925 1195,-915 3130,-915 10595,-915 4355,-910 9330,-910 10235,-900 2775,-895 4525,-895 10290,-895 7785,-880 1203.15,-876 5075,-865 5465,-865 7425,-865 5795,-860 10275,-860 4775,-850 1313.15,-845 8730,-845 1190,-840 7655,-840 5310,-835 10420,-835 11245,-835 4860,-830 10310,-830 1268.15,-826 8987.55,-825 11365,-825 9057.55,-820 9020.4,-819 5055,-810 5720,-795 8770,-795 8010,-790 585,-780 1025,-770 7950,-770 8974.55,-766.85 -145,-765 6440,-765 6150,-755 5216.85,-734.16 8765,-730 5126.85,-729.16 9062.55,-726.85 8987.55,-725 4855,-720 6540,-720 9033.55,-716.85 4460,-705 1445,-700 5235,-696.16 5130.85,-692.01 4705,-690 1025,-685 4780,-680 1605,-675 8785,-670 6300,-660 10670,-660 9165,-657.85 5136.85,-654.16 6445,-645 5216.85,-644.16 5175,-638.16 11195,-635 2743.15,-630 3680,-620 5590,-620 5695,-620 10665,-620 3870,-615 5645,-615 11355,-615 1530,-610 11045,-605 -65,-600 1380,-600 1430,-600 1475,-600 10705,-600 8730,-595 6925,-580 10670,-580 10725,-570 1000,-560 4270,-560 8365,-560 8655,-535 5438.15,-525 10715,-525 10835,-525 5500,-522.85 650,-515 685,-515 -150,-510 1343.15,-505 9285,-482.85 6500,-480 7070,-480 9133.15,-475 10975,-475 11185,-475 11355,-470 3008.15,-465 4265,-460 2295,-447.85 9963.15,-445 6855,-345 6850,-310 6605,-300 2788.15,-280 6855,-270 6685,-260 6720,-260 11375,-260 6610,-255 -60,-240 10053.15,-230 6745,-210 7010,-190 6185,-185 6695,-170 -140,-165 6230,-120 6710,-115 2478.15,-100 7055,-90 3418.15,-85 2965,-82.85 7305,-60 10725,-60 10965,-60 10530,-50 8233.15,75 9135,77.15 9670,77.15 1245,80 2085,80 2310,80 4478.15,80 4770,82.15 5500,82.15 5865,82.15 8660,82.15 270,85 455,85 685,85 965,85 1530,85 1825,85 5098.15,85 6410,85 7085,90 7260,90 6660,105 10730,120 10500,125 150,130 10975,130 2425,135 4015,135 10145,135 2610,140 3075,140 3310,140 3565,140 3690,140 2855,145
  other v2: 7080,-1175 6985,-1105 7080,-1105 6890,-1025 6985,-1025 7080,-1025 6890,-945 6985,-945 7080,-945 6890,-865 7080,-865 2660,-835
  other v5: 6985,-865
IO1: J1.4 J7.4 R14.2 R302.2 | length 195.4
  Top w6: J1.4@6545,-1865 6545,-1840 6570,-1815 R14.2@6570,-1720 R302.2@6610,-1720
IO2: J1.6 R15.2 R301.2 | length 205.7
  Top w8: R15.2@6655,-1720 R301.2@6695,-1720 6695,-1760 6740,-1805 6740,-1860 J1.6@6745,-1865
IO3: J1.7 R16.2 R300.2 | length 216.9
  Top w8: R16.2@6735,-1720 6780,-1720 6780,-1755 6845,-1820 J1.7@6845,-1865
MAC_MDC: C59.2 R53.1 R60.2 U8.30 | length 531.4
  Top w5: R53.1@4730,-455 C59.2@4810,-455 4810,-470 4835,-495 5130,-495 5192.87,-557.87 U8.30@5192.87,-575.04
MAC_MDIO: C60.2 R54.1 R62.2 U8.31 | length 587.3
  Top w5: R62.2@4650,-455 4685,-455 R54.1@4730,-500 4825,-500 4833.5,-508.5 5128.5,-508.5 5177.13,-557.13 U8.31@5177.13,-575.04
NetB3_1: B3.1 C28.1 C29.1 C30.1 U8.44 U8.45 | length 443
  Top w10: U8.45@5070.04,-729.37 5034.37,-729.37 5030,-725 5040,-715 5040,-713.62 U8.44@5070.04,-713.62
  Top w18: B3.1@4710,-750.47 4810,-750.47 ; C30.1@4785,-750.47 4810,-750.47 ; 5030,-725 4925,-725 4899.53,-750.47 4810,-750.47
NetB4_2: B4.2 C38.1 C39.1 C40.1 L3.1 U8.28 U8.36 | length 1041.9
  Top w8: v1(5080,-565) 5098.39,-565 U8.36@5098.39,-575.04 ; v1(5215,-525) 5224.37,-534.37 U8.28@5224.37,-575.04
  Top w15: v1(4820,-885) 4820,-910 4849.53,-939.53 C40.1@4860,-939.53 ; v1(4820,-635) 4890,-565 v1(5080,-565)
  Top w18: C40.1@4860,-939.53 B4.2@5020,-939.53
  Bottom w15: v1(4820,-885) v1(4820,-635) ; v1(5080,-565) 5090,-555 C38.1@5110,-555 C39.1@5225,-555 5225,-535 v1(5215,-525)
NetB6_1: B6.1 C62.1 C63.1 C64.1 U11.44 U11.45 | length 368.6
  Top w8: U11.44@1286.77,-995.8 1286.77,-1031.77 1295,-1040 ; 1295,-1042.52 1302.52,-1035 U11.45@1302.52,-995.8
  Top w18: B6.1@1224.53,-1240 C64.1@1295.47,-1240 1295,-1239.53 1295,-1042.52 1295,-1040
NetB7_2: B7.2 C72.1 C73.1 C74.1 L4.1 U11.28 U11.36 | length 1373.3
  Top w8: v1(1090,-970) 1092.55,-967.45 U11.36@1148.19,-967.45
  Top w10: v1(1085,-835) 1091.47,-841.47 U11.28@1148.19,-841.47
  Top w18: v1(1090,-970) 995,-1065 995,-1232.52 1067.48,-1305 1470,-1305 1514.53,-1260.47 C74.1@1514.53,-1225 ; C74.1@1514.53,-1220 1515,-1219.53 L4.1@1515,-1145 1514.53,-1144.53 B7.2@1514.53,-1070
  Bottom w8: C72.1@1057.68,-965.84 1058.52,-965 1065,-965 1070,-970 v1(1090,-970)
  Bottom w10: C73.1@1057.68,-835.84 C73.1@1058.52,-835
  Bottom w15: C72.1@1057.68,-965.84 C73.1@1057.68,-835.84
  Bottom w16: C73.1@1058.52,-835 v1(1085,-835)
NetB9_1: B9.1 C96.1 C97.1 C98.1 U14.44 U14.45 | length 423
  Top w10: U14.44@9047.01,-881.81 9047.5,-882.3 9047.5,-910.49 9062.76,-925.75 U14.45@9062.76,-881.81
  Top w18: v1(9055,-1080) C98.1@9094.53,-1080 ; C97.1@9055,-980 9055,-960 ; 9055,-925 9055,-960 ; C98.1@9095,-1080.47 C98.1@9094.53,-1080 ; 9055,-960 C96.1@9055,-1020 9055,-1040.47 C98.1@9094.53,-1080
  Bottom w18: B9.1@8974.53,-1040 9015,-1040 v1(9055,-1080)
NetB10_2: B10.2 C106.1 C107.1 C108.1 L5.1 U14.28 U14.36 | length 1267
  Top w8: v1@8872.55,-853.46 U14.36@8908.43,-853.46
  Top w10: 8855.03,-727.48 U14.28@8908.43,-727.48
  Top w15: v1(9056.5,-570) 9058,-568.5 9138.5,-568.5 v1(9160,-590) ; B10.2@9290,-895 B10.2@9284.53,-895 9314.53,-865 v1(9320,-865)
  Top w18: C108.1@9274.53,-1050 9275,-1049.53 L5.1@9275,-970 ; L5.1@9282.5,-977.5 9284.53,-975.47 B10.2@9284.53,-905
  Bottom w10: v1(8847.55,-720) 8868.02,-720 C106.1@8878.02,-730
  Bottom w15: v1(8847.55,-720) 8847.55,-637.45 8915,-570 v1(9056.5,-570) ; v1(8872.55,-855) 8878.02,-849.53 C106.1@8878.02,-730 ; v1(9160,-590) 9220,-590 9320,-690 v1(9320,-865)
NetB12_1: B12.1 B13.1 J1.1 J7.1 | length 225.5
  Top w20: J7.1@6245,-1865 B12.1@6245,-1714.53 B13.1@6320,-1714.53
NetC7_2: C7.2 U3.8 | length 73
  Top w12: U3.8@10818.26,-565.05 10844.95,-565.05 10860,-550 C7.2@10885,-550
NetC8_2: C8.2 U4.8 | length 68
  Top w12: U4.8@10533.26,-965.05 10559.95,-965.05 10575,-950 C8.2@10595,-950
NetC9_1: C9.1 R2.2 U3.1 | length 165.3
  Top w12: R2.2@10495,-655 C9.1@10495,-565 C9.1@10495,-565 U3.1@10570.23,-565.05
NetC10_1: C10.1 R3.2 U4.1 | length 160.2
  Top w15: C10.1@10215,-965 U4.1@10285.23,-965.05
  Top w24: R3.2@10215,-1055 C10.1@10215,-965
NetC11_1: C11.1 U5.1 | length 102.2
  Top w18: U5.1@6794.6,-260.78 6794.6,-225.4 6810,-210 C11.1@6855,-210
NetC11_2: C11.2 L1.1 U5.6 | length 322
  Top w5: L1.1@6988.18,-63.18 6988.18,11.73 L1.1@6988.56,12.11
  Top w24: C11.2@6895,-215 6895,-260 U5.6@6895.78,-260.78 ; C11.2@6895,-210 6979.9,-125.1 L1.1@6979.9,-44.71
NetC18_1: C18.1 C19.1 L1.2 L2.1 R9.1 R10.1 | length 560.4
  Top w5: L1.2@6763.66,-23.18 6798.95,12.11 L1.2@6787.77,12.11
  Top w15: L2.1@6610,-150 6645.51,-185.51 R10.1@6645.51,-292.35 R9.1@6685.51,-292.35
  Top w60: L2.1@6610,-150 6610,-25 6759.41,-25 L1.2@6779.12,-44.71
NetC44_1: C44.1 T1.1 T1.4 T1.7 T1.10 | length 859.7
  Top w15: T1.10@5575,-1140.04 5575,-1210 5600,-1235 5725,-1235 ; T1.7@5725,-1140.04 5725,-1235 ; T1.4@5875,-1140.04 5875,-1235 ; T1.1@6025,-1140.04 v1(6025,-1200) 5990,-1235 5875,-1235 ; 5725,-1235 5875,-1235
  Bottom w15: v1(6025,-1200) C44.1@6025,-1135
NetC47_1: C47.1 R24.2 R25.2 R26.2 R32.2 | length 515
  Bottom w24: R24.2@5580,-1640 C47.1@6095,-1640
NetC54_2: C54.2 R34.2 R35.2 U8.29 | length 388
  Top w5: R34.2@4880,-455 4960,-455 4990,-485 5135,-485 5208.62,-558.62 U8.29@5208.62,-575.04
NetC86_1: C86.1 T2.1 T2.4 T2.7 T2.10 | length 844.5
  Top w18: T2.10@2118.15,-710.88 2118.15,-785 2138.15,-805 2268.15,-805 ; T2.7@2268.15,-710.88 2268.15,-805 ; T2.4@2418.15,-710.88 2418.15,-805 ; T2.1@2568.15,-710.88 2568.15,-766.85 v1(2565,-770) 2530,-805 2418.15,-805 ; 2268.15,-805 2418.15,-805
  Bottom w18: v1(2565,-770) 2570,-765 C86.1@2570,-720
NetC87_1: C87.1 R84.2 R85.2 R86.2 R92.2 | length 645
  Bottom w24: C87.1@1925,-1210 R92.2@2570,-1210
NetC88_2: C88.2 R94.2 R95.2 U11.29 | length 421.2
  Top w5: R95.2@960,-600 R94.2@960,-640 C88.2@1000,-640 1035,-640 1065,-670 1065,-845.86 1076.36,-857.22 U11.29@1148.19,-857.22
NetC112_1: C112.1 T3.1 T3.4 T3.7 T3.10 | length 821.3
  Top w18: T3.10@9528.15,-650.88 9528.15,-718.15 9550,-740 9678.15,-740 ; T3.7@9678.15,-650.88 9678.15,-740 ; T3.4@9828.15,-650.88 9828.15,-740 ; v1(9977.7,-714.08) v1@9977.7,-722.3 ; T3.1@9978.15,-650.88 9978.15,-721.85 v1@9977.7,-722.3 ; 9678.15,-740 9828.15,-740 ; 9828.15,-740 9960,-740 v1@9977.7,-722.3
  Bottom w18: v1(9977.7,-714.08) 9977.7,-687.3 C112.1@9980,-685
NetC121_1: C121.1 R144.2 R145.2 R146.2 R152.2 | length 525
  Bottom w25: C121.1@9455,-1150 R152.2@9980,-1150
NetC122_2: C122.2 R154.2 R155.2 U14.29 | length 295.8
  Top w5: R155.2@8685,-625 R154.2@8685,-665 C122.2@8730,-665 8750,-665 8828.23,-743.23 U14.29@8908.43,-743.23
NetF1_2: F1.2 J12.1 J12.2 J13.1 J13.2 | length 961.8
  Top w40: J13.1@1045.3,-1919.72 J13.2@1130.3,-1919.72 1130.3,-1930.3 1195,-1995 1500,-1995 1567.78,-1927.22 1580.3,-1927.22 J12.1@1587.8,-1927.22 ; F1.2@1500.55,-1700 1510,-1700 1587.8,-1777.8 J12.1@1587.8,-1912.22 ; J12.1@1580.3,-1919.72 J12.2@1680.3,-1919.72
NetF2_2: F2.2 J10.1 J10.2 J11.1 J11.2 | length 932.6
  Top w40: J11.1@-59.7,-1919.72 J11.2@35.3,-1919.72 J11.2@40.3,-1919.72 ; F2.2@49.45,-1700 49.45,-1910.57 J11.2@40.3,-1919.72 ; J10.2@595.3,-1919.72 J10.2@585.3,-1919.72 495.3,-1919.72 490.3,-1924.72 485.3,-1924.72 480.28,-1924.72 420,-1985 105.58,-1985 J11.2@40.3,-1919.72
NetJ1_8: J1.8 R303.2 R304.2 | length 222.3
  Top w8: R304.2@6815,-1720 R303.2@6855,-1720 6855,-1775 J1.8@6945,-1865
NetJ2_19: J2.19 R99.2 R101.2 | length 1998.1
  Top w5: R101.2@1835,-1425 R99.2@1795,-1425 1795,-1647.57 2162.43,-2015 v1(3135,-2015)
  Bottom w5: v1(3135,-2015) J2.19@3135,-1771.65
NetJ2_20: J2.20 R97.2 R98.2 | length 2223.9
  Top w5: R97.2@1665,-1425 R98.2@1710,-1425 1710,-1576.72 2164.78,-2031.5 3163.5,-2031.5 v1(3180,-2015)
  Bottom w5: J2.20@3135,-1671.65 3180,-1716.65 v1(3180,-2015)
NetJ2_21: J2.21 R38.2 R40.2 | length 463.8
  Top w5: R40.2@3045,-1410 R38.2@3085,-1410 3085,-1470 3185,-1570 3185,-1721.65 J2.21@3235,-1771.65
NetJ2_22: J2.22 R36.2 R37.2 | length 314.1
  Top w5: R37.2@3165,-1410 R36.2@3205,-1410 3205,-1440 3235,-1470 J2.22@3235,-1671.65
NetJ2_23: J2.23 R104.2 R105.2 | length 2314.1
  Top w5: R104.2@1575,-1425 R105.2@1615,-1425 1615,-1495.86 2160.64,-2041.5 3313.5,-2041.5 v1(3335,-2020)
  Bottom w5: v1(3335,-2020) J2.23@3335,-1771.65
NetJ2_24: J2.24 R102.2 R103.2 | length 2605.6
  Top w5: R102.2@1440,-1425 1470,-1455 1500,-1455 R103.2@1530,-1425 2156.5,-2051.5 3343.5,-2051.5 v1(3370,-2025)
  Bottom w5: J2.24@3335,-1671.65 3385,-1721.65 3385,-2010 v1(3370,-2025)
NetJ2_25: J2.25 R44.2 R45.2 | length 455.5
  Top w5: R44.2@3365,-1410 R45.2@3405,-1410 3405,-1545 3485,-1625 3485,-1721.65 J2.25@3435,-1771.65
NetJ2_26: J2.26 R41.2 R42.2 | length 417.9
  Top w5: R41.2@3245,-1410 3245,-1420 3265,-1440 3295,-1440 R42.2@3325,-1410 3325,-1561.65 J2.26@3435,-1671.65
NetJ3_19: J3.19 R159.2 R161.2 | length 5542.1
  Top w5: v1(6945,-1700) 7000,-1755 7865.86,-1755 8010.86,-1900 9287.43,-1900 9365,-1822.43 9365,-1555.86 9270,-1460.86 R159.2@9270,-1260 R161.2@9310,-1260
  Bottom w5: J3.19@4830,-1771.65 4830,-1790 4890,-1850 5199.14,-1850 5524.14,-1525 6770,-1525 v1(6945,-1700)
NetJ3_20: J3.20 R157.2 R158.2 | length 5575.1
  Top w5: v1(6945,-1675) 7015,-1745 7870,-1745 8015,-1890 9283.28,-1890 9355,-1818.28 9355,-1560 9260,-1465 9260,-1335 R157.2@9235,-1310 9230,-1305 R158.2@9230,-1260
  Bottom w5: J3.20@4830,-1671.65 4836.65,-1671.65 4880,-1715 4880,-1810 4910,-1840 5195,-1840 5520,-1515 6780,-1515 v1@6940,-1675
NetJ3_23: J3.23 R164.2 R165.2 | length 5238.4
  Top w5: v1(6990,-1660) 7055,-1725 7880,-1725 8022,-1867 9278,-1867 9335,-1810 9335,-1575 R164.2@9110,-1350 R165.2@9070,-1350
  Bottom w5: J3.23@5030,-1771.65 5030,-1785 5065,-1820 5185,-1820 5510,-1495 6825,-1495 v1(6990,-1660)
NetJ3_24: J3.24 R162.2 R163.2 | length 5412.1
  Top w5: v1(6985,-1685) 7035,-1735 7875,-1735 8020,-1880 9279.14,-1880 9345,-1814.14 9345,-1565 9190,-1410 R162.2@9190,-1350 R163.2@9150,-1350
  Bottom w5: J3.24@5030,-1671.65 4980,-1721.65 4980,-1800 5010,-1830 5189.14,-1830 5514.14,-1505 6805,-1505 v1(6985,-1685)
NetJ6_18: J6.18 U7.69 | length 3546.6
  Top w5: v1(6000,-540) 6000,-901.86 6265,-1166.86 v1(6265,-1430) ; v1(6090,-540) 6135,-540 6160,-565 6811.7,-565 6841.7,-595 U7.69@6841.7,-640.27
  Bottom w5: J6.18@4783.47,-1141.73 4820,-1178.27 4820,-1240 4875.79,-1295.79 5255.79,-1295.79 5390,-1430 v1(6265,-1430) ; v1(6000,-540) v1(6090,-540)
NetJ6_19: J6.19 U7.70 | length 3322.7
  Top w5: v1(5980,-560) 5980,-896.01 6245,-1161.01 v1(6245,-1410) ; v1(6105,-560) 6135,-560 6150,-575 6800,-575 6822.01,-597.01 U7.70@6822.01,-640.27
  Bottom w5: J6.19@4862.21,-1220.47 4862.21,-1222.21 4925.79,-1285.79 5265.79,-1285.79 5390,-1410 v1(6245,-1410) ; v1(5980,-560) v1(6105,-560)
NetJ6_20: J6.20 U7.71 | length 3122.2
  Top w5: v1(5880,-585) 5880,-895 6110,-1125 v1(6110,-1270) ; v1(6100,-585) 6792.33,-585 6802.33,-595 U7.71@6802.33,-640.27
  Bottom w5: J6.20@4862.21,-1141.73 4862.21,-1117.79 4905,-1075 5190,-1075 5385,-1270 v1(6110,-1270) ; v1(5880,-585) v1(6100,-585)
NetJ6_21: J6.21 U7.66 | length 3397.9
  Top w5: v1(5995,-480) 5995,-510 5960,-545 5960,-890.15 6225,-1155.15 v1(6225,-1390) ; v1(6105,-480) 6125,-480 6180,-535 6840,-535 6900.75,-595.75 U7.66@6900.75,-640.27
  Bottom w5: J6.21@4940.95,-1220.47 4940.95,-1230.95 4985.79,-1275.79 5275.79,-1275.79 5390,-1390 6115,-1390 ; v1(5995,-480) v1(6105,-480) ; 6120,-1390 6115,-1390 ; v1(6225,-1390) 6115,-1390
NetJ6_22: J6.22 U7.68 | length 3196.7
  Top w5: v1(5900,-525) 5900,-900.86 6130,-1130.86 v1(6130,-1285) ; v1(6105,-520) 6132,-520 6167,-555 6821.38,-555 6861.38,-595 U7.68@6861.38,-640.27
  Bottom w5: J6.22@4940.95,-1141.73 4940.95,-1119.05 4970,-1090 5190,-1090 5390,-1290 v1@6125,-1290 ; v1(5900,-525) 5903.5,-521.5 6103.5,-521.5 v1(6105,-520)
NetJ6_23: J6.23 U7.67 | length 3223.9
  Top w5: v1(5975,-500) 5950,-525 5950,-894.29 6205,-1149.29 v1(6205,-1370) ; v1(6090,-500) 6130,-500 6175,-545 6831.07,-545 6881.07,-595 U7.67@6881.07,-640.27
  Bottom w5: J6.23@5019.69,-1220.47 5065,-1265.79 5285.79,-1265.79 5390,-1370 v1(6205,-1370) ; v1(5975,-500) v1(6090,-500)
NetJ6_24: J6.24 U7.55 | length 3672.9
  Top w5: v1(5950,-415) 5920,-445 5920,-906.72 6150,-1136.72 v1(6150,-1305) ; v1(6095,-415) 6105,-415 6195,-505 6816.72,-505 6896.72,-425 7088.28,-425 7115,-451.72 7115,-637.98 U7.55@7117.29,-640.27
  Bottom w5: J6.24@5019.69,-1141.73 5019.69,-1130.31 5050,-1100 5180,-1100 5385,-1305 v1(6150,-1305) ; v1(5950,-415) v1(6095,-415)
NetJ6_25: J6.25 U7.57 | length 3521.6
  Top w5: v1(5975,-460) 5940,-495 5940,-898.43 6186.5,-1144.93 6186.5,-1348.5 v1(6185,-1350) ; v1(6088.74,-461.26) 6090,-460 6120,-460 6185,-525 6825,-525 6905,-445 7080,-445 7095,-460 7095,-583.15 7077.92,-600.23 U7.57@7077.92,-640.27
  Bottom w5: J6.25@5098.43,-1220.47 5260.47,-1220.47 5390,-1350 v1(6185,-1350) ; v1@5975,-461.26 v1(6088.74,-461.26)
NetJ6_26: J6.26 U7.56 | length 3554.6
  Top w5: v1(5960,-440) 5930,-470 5930,-902.57 6170,-1142.57 v1(6170,-1325) v1@6170,-1330 ; v1(6100,-440) 6115,-440 6190,-515 6820.86,-515 6900.86,-435 7084.14,-435 7105,-455.86 7105,-587.29 7097.6,-594.68 U7.56@7097.6,-640.27
  Bottom w5: J6.26@5098.43,-1141.73 5106.69,-1150 5210,-1150 5385,-1325 v1(6170,-1325) ; v1(5960,-440) v1(6100,-440)
NetJ9_1: J9.1 U7.2 | length 1040.7
  Top w5: U7.2@6743.27,-1246.56 6743.27,-1408.27 6885,-1550 6885,-1717.43 7032.57,-1865 J9.1@7310,-1865 J9.1@7310,-1890
NetJ9_2: J9.2 U7.3 | length 1122.7
  Top w5: U7.3@6762.96,-1246.56 6762.96,-1412.96 6895,-1545 6895,-1713.28 7001.72,-1820 7363.43,-1820 J9.2@7408.43,-1865 J9.2@7408.43,-1890
NetJ9_3: J9.3 U7.4 | length 1204.7
  Top w5: U7.4@6782.64,-1246.56 6782.64,-1417.64 6905,-1540 6905,-1709.14 7005.86,-1810 7446.85,-1810 7501.85,-1865 J9.3@7506.85,-1865 J9.3@7506.85,-1890
NetJ9_4: J9.4 U7.5 | length 1286.7
  Top w5: U7.5@6802.33,-1246.56 6802.33,-1422.33 6915,-1535 6915,-1705 7010,-1800 7540.28,-1800 J9.4@7605.28,-1865 J9.4@7605.28,-1890
NetJ14_2: J14.2 R500.1 U7.6 | length 513.2
  Top w5: U7.6@6822.01,-1246.56 6822.01,-1402.01 R500.1@6835,-1415 6920,-1500 7035,-1500 7093.43,-1558.43 J14.2@7093.43,-1580
NetJP1_A1: JP1.A1 R75.1 | length 2928.7
  Top w5: v1(4535,-25) 4593.16,33.16 5878.41,33.16 6060,-148.43 6060,-888.43 6276.57,-1105 R75.1@6350,-1105
  Bottom w5: JP1.A1@4387.8,-115.41 4478.2,-25 v1(4535,-25)
NetJP1_A2: JP1.A2 R76.1 | length 2840.1
  Top w5: v1(4610,-25) 4658.16,23.16 5874.27,23.16 6050,-152.57 6050,-892.57 6302.43,-1145 R76.1@6350,-1145
  Bottom w5: JP1.A2@4490,-113.2 JP1.A2@4487.8,-115.41 4578.2,-25 v1(4610,-25)
NetJP1_B1: JP1.B1 JP1.B2 JP1.B3 JP1.B4 LED1.A U10.5 U10.6 U10.7 U10.8 U10.9 | length 1172.9
  Top w30: U10.5@3868.62,-515.84 v3(3943.15,-515.84) 4034.1,-515.84 LED1.A@4035.32,-514.61 ; U10.6@3868.62,-465.84 v3(3943.15,-465.84) ; U10.7@3868.62,-415.84 v3(3943.15,-415.84) ; U10.8@3868.62,-365.84 v3(3943.15,-365.84)
  Bottom w5: v3(3943.15,-365.84) 4157.72,-365.84 4248.15,-275.41 ; 4248.15,-215.41 JP1.B2@4487.8,-215.41 JP1.B3@4587.8,-215.41 JP1.B4@4687.8,-215.41
  other v1: 3739,-514 3775,-514 3810,-514 3741,-480 3775,-480 3811,-480 3811,-446 3741,-443 3775,-442 3812,-409 3741,-408 3776,-408 3777,-373 3742,-372 3813,-372
NetJP1_C1: JP1.C1 R406.1 R411.1 | length 179.6
  Bottom w8: R411.1@4360,-450 R406.1@4400,-450 4400,-327.61 JP1.C1@4387.8,-315.41
NetJP1_C2: JP1.C2 R407.1 R410.1 | length 180.8
  Bottom w8: R410.1@4440,-450 R407.1@4485,-450 4485,-318.2 JP1.C2@4487.8,-315.41
NetJP1_C3: JP1.C3 R408.1 R409.1 | length 182
  Bottom w8: R408.1@4530,-450 R409.1@4570,-450 4570,-375 4587.8,-357.2 JP1.C3@4587.8,-315.41
NetJP2_A1: JP2.A1 R135.1 | length 7166.6
  Top w5: JP2.A1@509.84,-115.13 509.84,-40.16 579,29 1976,29 2150,-145 2150.86,-145 2210.86,-205 3376.72,-205 3461.72,-290 4133.28,-290 4368.28,-55 4639.14,-55 4697.3,3.16 5865.99,3.16 6030,-160.86 6030,-900.86 6286,-1156.86 6286,-1196 6325,-1235 R135.1@6350,-1235
NetJP2_A2: JP2.A2 R137.1 | length 7151.7
  Top w5: JP2.A2@609.84,-115.13 609.84,-30.16 659,19 1971,19 2145,-155 2146.72,-155 2206.72,-215 3372.57,-215 3457.57,-300 4137.43,-300 4372.43,-65 4643.28,-65 4701.44,-6.84 5861.84,-6.84 6020,-165 6020,-905 6275.15,-1160.15 6275.15,-1292.15 6298,-1315 R137.1@6350,-1315
NetJP2_B1: JP2.B1 JP2.B2 JP2.B3 JP2.B4 LED2.A U13.5 U13.6 U13.7 U13.8 U13.9 | length 998.6
  Top w18: v3(480.24,-485.21) 565.27,-485.21 LED2.A@585.39,-505.32
  Top w30: U13.8@330.24,-544.74 v3(330.24,-485.21) ; U13.7@380.24,-544.74 v3(380.24,-485.21) ; U13.6@430.24,-544.74 v3(430.24,-485.21) ; U13.5@480.24,-544.74 v3(480.24,-485.21)
  Bottom w5: v3(380.24,-485.21) 380.24,-305.13 470.24,-215.13 609.84,-215.13 709.84,-215.13 JP2.B4@809.84,-215.13
  other v1: 335,-672 368,-670 403,-670 438,-668 475,-668 335,-632 367,-632 405.04,-630.37 439,-629 476,-629 370,-600 408,-600 334,-599 441,-599 478,-599
NetJP2_C1: JP2.C1 R403.1 R414.1 | length 179.9
  Bottom w8: JP2.C1@509.84,-315.52 535,-340.68 R403.1@535,-445 R414.1@575,-445
NetJP2_C2: JP2.C2 R404.1 R413.1 | length 171.8
  Bottom w8: JP2.C2@610,-315.68 JP2.C2@609.84,-315.52 615,-320.68 R413.1@615,-445 R404.1@655,-445
NetJP2_C3: JP2.C3 R405.1 R412.1 | length 175.6
  Bottom w8: JP2.C3@709.84,-315.52 695,-330.37 R405.1@695,-445 R412.1@735,-445
NetJP3_A1: JP3.A1 R195.1 | length 1280.7
  Top w5: R195.1@7255,-510 7255,-420 7331,-344 7331,-252.14 7363.14,-220 8039.14,-220 8143.62,-115.52 JP3.A1@8265.75,-115.52
NetJP3_A2: JP3.A2 R196.1 | length 1459.8
  Top w5: R196.1@7175,-510 7175,-483 7321,-337 7321,-248 7359,-210 8035,-210 8175,-70 8320.22,-70 JP3.A2@8365.75,-115.52
NetJP3_B1: JP3.B1 JP3.B2 JP3.B3 JP3.B4 LED4.A U16.5 U16.6 U16.7 U16.8 U16.9 | length 1007.7
  Top w5: U16.6@8056.15,-374.84 U16.6@8061.62,-374.84
  Top w20: v3(8131.15,-424.84) 8131.15,-374.84 8131.15,-324.84 8131.15,-274.84 8190.47,-215.52 JP3.B2@8365.75,-215.52
  Top w24: U16.6@8056.15,-374.84 8131.15,-374.84 ; U16.5@8061.62,-424.84 v3(8131.15,-424.84) 8205.55,-424.84 LED4.A@8230.32,-449.61 ; U16.7@8061.62,-324.84 8131.15,-324.84 ; U16.8@8061.62,-274.84 8131.15,-274.84
  Bottom w50: JP3.B2@8365.75,-215.13 8465.75,-215.13 JP3.B4@8565.75,-215.13
  other v1: 8002,-422 7931,-421 7963,-421 7964,-391 7998,-391 7933,-390 7996,-356 7934,-355 7965,-355 7996,-320 7966,-319 7935,-318 7933,-281 7967,-281 7998,-280
NetJP3_C1: JP3.C1 R400.1 R417.1 | length 225.4
  Bottom w8: JP3.C1@8265.75,-315.52 8280,-329.78 R400.1@8280,-495 R417.1@8320,-495
NetJP3_C2: JP3.C2 R401.1 R416.1 | length 219.8
  Bottom w8: JP3.C2@8365.75,-315.52 8365.75,-494.25 R401.1@8365,-495 R416.1@8405,-495
NetJP3_C3: JP3.C3 R402.1 R415.1 | length 228.1
  Bottom w8: JP3.C3@8465.75,-315.52 8465.75,-424.25 8445,-445 R415.1@8445,-495 R402.1@8485,-495
NetJTAG1_1: JTAG1.1 R19.2 U7.24 | length 758.7
  Top w5: U7.24@7176.34,-1246.56 7176.34,-1318.66 7195,-1337.31 7195,-1355 R19.2@7210,-1355 ; 7225,-1355 R19.2@7210,-1355 ; v1(7560,-1445) 7558,-1445 7548,-1435 7294.86,-1435 7265,-1405.14 7265,-1364.14 7255.86,-1355 R19.2@7210,-1355
  Bottom w5: v1(7560,-1445) 7690,-1445 7705,-1460 JTAG1.1@7705,-1510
